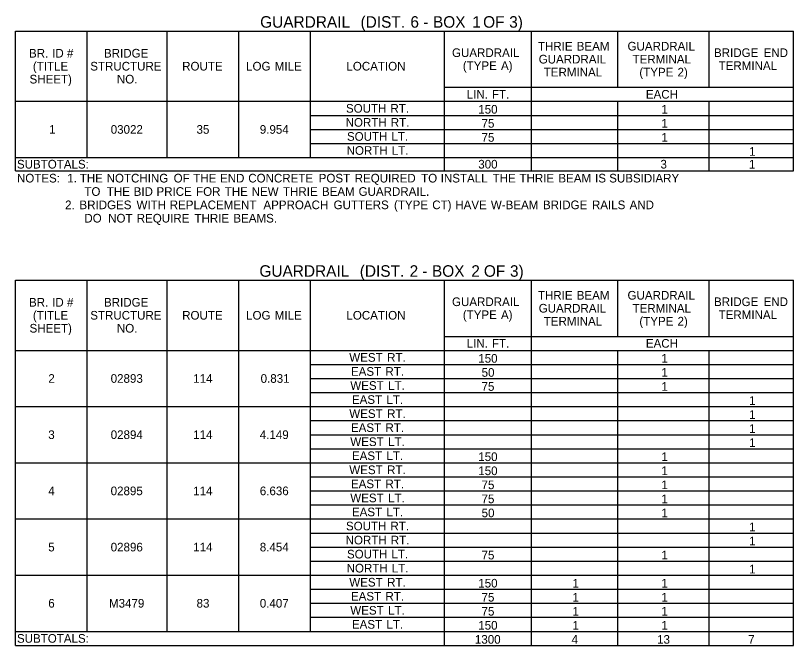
# Model space of a CAD drawing. Extents: x 542596 to 1930787, y -1948294 to 596640.
# Drawn here: x 546811 to 547351, y -1946617 to -1946180 of the extents above; entities that cross this region are included whole.
import ezdxf

# ---------------------------------------------------------------- set-up
doc = ezdxf.new("R2010")
doc.units = 0
doc.layers.add('Default', color=7, linetype='Continuous')

msp = doc.modelspace()

# ---------------------------------------------------------------- linework, layer by layer
at = {"layer": 'Default'}
for p, q in [((546810.99, -1946190.4), (547351.14, -1946190.4)), ((546810.99, -1946287.41), (546810.99, -1946190.4)), ((546810.99, -1946287.41), (546810.99, -1946190.4)), ((546860.71, -1946278.15), (546860.71, -1946190.4)), ((546916.29, -1946278.15), (546916.29, -1946190.4)), ((546966.01, -1946278.15), (546966.01, -1946190.4)), ((547015.74, -1946278.15), (547015.74, -1946190.4)), ((547108.85, -1946287.41), (547108.85, -1946190.4)), ((547169.3, -1946287.41), (547169.3, -1946190.4)), ((547229.26, -1946229.4), (547229.26, -1946190.4)), ((547292.64, -1946229.4), (547292.64, -1946190.4)), ((547351.14, -1946287.41), (547351.14, -1946190.4)), ((547108.85, -1946229.4), (547351.14, -1946229.4)), ((547169.3, -1946278.15), (547169.3, -1946229.4)), ((546810.99, -1946239.15), (547351.14, -1946239.15)), ((547229.26, -1946278.15), (547229.26, -1946239.15)), ((547229.26, -1946287.41), (547229.26, -1946239.15)), ((547292.64, -1946278.15), (547292.64, -1946239.15)), ((547292.64, -1946287.41), (547292.64, -1946239.15)), ((547015.74, -1946248.9), (547351.14, -1946248.9)), ((547015.74, -1946258.65), (547351.14, -1946258.65)), ((547015.74, -1946268.4), (547351.14, -1946268.4)), ((546810.99, -1946278.15), (547292.64, -1946278.15)), ((546810.99, -1946278.15), (547229.26, -1946278.15)), ((547229.26, -1946278.15), (547351.14, -1946278.15)), ((546810.99, -1946287.41), (547351.14, -1946287.41)), ((546810.99, -1946363.24), (547351.14, -1946363.24)), ((546810.99, -1946616.74), (546810.99, -1946363.24)), ((546810.99, -1946616.74), (546810.99, -1946363.24)), ((546860.71, -1946606.99), (546860.71, -1946363.24)), ((546916.29, -1946606.99), (546916.29, -1946363.24)), ((546966.01, -1946606.99), (546966.01, -1946363.24)), ((547015.74, -1946606.99), (547015.74, -1946363.24)), ((547108.85, -1946616.74), (547108.85, -1946363.24)), ((547169.3, -1946616.74), (547169.3, -1946363.24)), ((547229.26, -1946402.24), (547229.26, -1946363.24)), ((547292.64, -1946402.24), (547292.64, -1946363.24)), ((547351.14, -1946606.99), (547351.14, -1946363.24)), ((547108.85, -1946402.24), (547351.14, -1946402.24)), ((547169.3, -1946616.74), (547169.3, -1946402.24)), ((546810.99, -1946411.99), (547351.14, -1946411.99)), ((547229.26, -1946616.74), (547229.26, -1946411.99)), ((547229.26, -1946616.74), (547229.26, -1946411.99)), ((547292.64, -1946616.74), (547292.64, -1946411.99)), ((547015.74, -1946421.74), (547351.14, -1946421.74)), ((547292.64, -1946431.49), (547292.64, -1946421.74)), ((547015.74, -1946431.49), (547351.14, -1946431.49)), ((547015.74, -1946441.24), (547351.14, -1946441.24)), ((547292.64, -1946450.99), (547292.64, -1946441.24)), ((546810.99, -1946450.99), (547351.14, -1946450.99)), ((546966.01, -1946450.99), (547108.85, -1946450.99)), ((547108.85, -1946450.99), (547351.14, -1946450.99)), ((547015.74, -1946460.74), (547351.14, -1946460.74)), ((547015.74, -1946470.49), (547351.14, -1946470.49)), ((547015.74, -1946480.24), (547351.14, -1946480.24)), ((546810.99, -1946489.99), (547351.14, -1946489.99)), ((547015.74, -1946489.99), (547108.85, -1946489.99)), ((547108.85, -1946489.99), (547351.14, -1946489.99)), ((547015.74, -1946499.74), (547351.14, -1946499.74)), ((547015.74, -1946509.49), (547351.14, -1946509.49)), ((547015.74, -1946519.24), (547351.14, -1946519.24)), ((547292.64, -1946528.99), (547292.64, -1946519.24)), ((546810.99, -1946528.99), (547351.14, -1946528.99)), ((547015.74, -1946528.99), (547108.85, -1946528.99)), ((547108.85, -1946528.99), (547351.14, -1946528.99)), ((547015.74, -1946538.74), (547351.14, -1946538.74)), ((547292.64, -1946548.49), (547292.64, -1946538.74)), ((547015.74, -1946548.49), (547351.14, -1946548.49)), ((547015.74, -1946558.24), (547351.14, -1946558.24)), ((546810.99, -1946567.99), (547351.14, -1946567.99)), ((547015.74, -1946567.99), (547108.85, -1946567.99)), ((547108.85, -1946567.99), (547351.14, -1946567.99)), ((547015.74, -1946577.74), (547351.14, -1946577.74)), ((547015.74, -1946587.49), (547351.14, -1946587.49)), ((547015.74, -1946597.24), (547351.14, -1946597.24)), ((546810.99, -1946606.99), (547351.14, -1946606.99)), ((547292.64, -1946616.74), (547292.64, -1946606.99)), ((547351.14, -1946616.74), (547351.14, -1946606.99)), ((546810.99, -1946616.74), (547351.14, -1946616.74))]:
    msp.add_line(p, q, dxfattribs=at)

# ---------------------------------------------------------------- texts
for s, height, p in [('GUARDRAIL', 8, (546980.84, -1946188.06)), (' (DIST.', 8, (547047.57, -1946188.06)), (' 6', 8, (547082.19, -1946188.06)), (' BOX', 8, (547097.86, -1946188.06)), (' 1', 8, (547125.17, -1946188.06)), (' OF', 8, (547132.68, -1946188.06)), (' 3)', 8, (547150.79, -1946188.06)), (' -', 8, (547091.11, -1946188.06)), ('THRIE', 6, (547173.71, -1946203.9)), (' BEAM', 6, (547198.44, -1946203.9)), ('GUARDRAIL', 6, (547235.93, -1946203.9)), ('BR.', 6, (546820.33, -1946208.77)), (' ID', 6, (546834.19, -1946208.77)), (' #', 6, (546844.48, -1946208.77)), ('BRIDGE', 6, (546872.4, -1946208.77)), ('GUARDRAIL', 6, (547114.05, -1946208.4)), ('BRIDGE', 6, (547295.98, -1946208.4)), (' END', 6, (547328.18, -1946208.4)), ('GUARDRAIL', 6, (547174.26, -1946212.9)), ('TERMINAL', 6, (547239.42, -1946212.9)), ('(TITLE', 6, (546823.02, -1946217.77)), ('STRUCTURE', 6, (546862.86, -1946217.77)), ('ROUTE', 6, (546926.68, -1946217.77)), ('LOG', 6, (546971.08, -1946217.77)), (' MILE', 6, (546988.73, -1946217.77)), ('LOCATION', 6, (547040.74, -1946217.77)), ('(TYPE', 6, (547121.57, -1946217.4)), (' A)', 6, (547145.84, -1946217.4)), ('TERMINAL', 6, (547299.19, -1946217.4)), ('TERMINAL', 6, (547177.75, -1946221.9)), ('(TYPE', 6, (547244.14, -1946221.9)), (' 2)', 6, (547268.42, -1946221.9)), ('SHEET)', 6, (546820.69, -1946226.77)), ('NO.', 6, (546881.34, -1946226.77)), ('LIN.', 6, (547124.29, -1946237.27)), (' FT.', 6, (547139.54, -1946237.27)), ('EACH', 6, (547248.66, -1946237.27)), ('SOUTH', 6, (547040.41, -1946247.02)), (' RT.', 6, (547069.08, -1946247.02)), ('150', 6, (547132.29, -1946247.7)), ('1', 6, (547259.39, -1946247.7)), ('NORTH', 6, (547040.18, -1946256.77)), (' RT.', 6, (547069.31, -1946256.77)), ('75', 6, (547134.58, -1946257.45)), ('1', 6, (547259.39, -1946257.45)), ('1', 6, (546834.29, -1946261.65)), ('03022', 6, (546877.07, -1946261.65)), ('35', 6, (546936.66, -1946261.65)), ('9.954', 6, (546980.59, -1946261.65)), ('SOUTH', 6, (547041.11, -1946266.52)), (' LT.', 6, (547069.78, -1946266.52)), ('75', 6, (547134.58, -1946267.2)), ('1', 6, (547259.39, -1946267.2)), ('NORTH', 6, (547040.88, -1946276.27)), (' LT.', 6, (547070.01, -1946276.27)), ('1', 6, (547320.33, -1946276.95)), ('SUBTOTALS:', 6, (546811.96, -1946285.78)), ('300', 6, (547132.29, -1946285.78)), ('3', 6, (547258.8, -1946285.78)), ('1', 6, (547320.24, -1946285.78)), ('NOTES:', 6, (546811.96, -1946295.47)), ('  1.', 6, (546842.44, -1946295.47)), (' THE', 6, (546853.35, -1946295.47)), (' NOTCHING', 6, (546872, -1946295.47)), (' OF', 6, (546918.52, -1946295.47)), (' THE', 6, (546932.1, -1946295.47)), (' END', 6, (546950.75, -1946295.47)), (' CONCRETE', 6, (546970.34, -1946295.47)), (' POST', 6, (547019.26, -1946295.47)), (' REQUIRED', 6, (547044.25, -1946295.47)), (' TO', 6, (547090.39, -1946295.47)), (' INSTALL', 6, (547103.98, -1946295.47)), (' THE', 6, (547140.02, -1946295.47)), (' THRIE', 6, (547158.67, -1946295.47)), (' BEAM', 6, (547185.7, -1946295.47)), (' IS', 6, (547211.16, -1946295.47)), (' SUBSIDIARY', 6, (547220.97, -1946295.47)), ('                     TO', 6, (546811.96, -1946304.74)), (' THE', 6, (546872.11, -1946304.74)), (' BID', 6, (546890.76, -1946304.74)), (' PRICE', 6, (546906.62, -1946304.74)), (' FOR', 6, (546934.12, -1946304.74)), (' THE', 6, (546954.03, -1946304.74)), (' NEW', 6, (546972.68, -1946304.74)), (' THRIE', 6, (546994.47, -1946304.74)), (' BEAM', 6, (547021.5, -1946304.74)), (' GUARDRAIL.', 6, (547046.96, -1946304.74)), ('               2.', 6, (546811.96, -1946314)), (' BRIDGES', 6, (546853.13, -1946314)), (' WITH', 6, (546892.76, -1946314)), (' REPLACEMENT', 6, (546915.83, -1946314)), (' APPROACH', 6, (546980.88, -1946314)), (' GUTTERS', 6, (547029.59, -1946314)), (' (TYPE', 6, (547071.54, -1946314)), (' CT)', 6, (547098.11, -1946314)), (' HAVE', 6, (547114.1, -1946314)), (' W-BEAM', 6, (547138.82, -1946314)), (' BRIDGE', 6, (547174.98, -1946314)), (' RAILS', 6, (547209, -1946314)), (' AND', 6, (547235.12, -1946314)), ('                     DO', 6, (546811.96, -1946323.26)), (' NOT', 6, (546873.05, -1946323.26)), (' REQUIRE', 6, (546892.9, -1946323.26)), (' THRIE', 6, (546932.98, -1946323.26)), (' BEAMS.', 6, (546960.01, -1946323.26)), ('GUARDRAIL', 8, (546980.3, -1946360.9)), (' (DIST.', 8, (547047.03, -1946360.9)), (' 2', 8, (547081.65, -1946360.9)), (' BOX', 8, (547097.15, -1946360.9)), (' 2', 8, (547124.47, -1946360.9)), (' OF', 8, (547133.22, -1946360.9)), (' 3)', 8, (547151.33, -1946360.9)), (' -', 8, (547090.41, -1946360.9)), ('THRIE', 6, (547173.71, -1946376.74)), (' BEAM', 6, (547198.44, -1946376.74)), ('GUARDRAIL', 6, (547235.93, -1946376.74)), ('BR.', 6, (546820.33, -1946381.62)), (' ID', 6, (546834.19, -1946381.62)), (' #', 6, (546844.48, -1946381.62)), ('BRIDGE', 6, (546872.4, -1946381.62)), ('GUARDRAIL', 6, (547114.05, -1946381.24)), ('BRIDGE', 6, (547295.98, -1946381.24)), (' END', 6, (547328.18, -1946381.24)), ('GUARDRAIL', 6, (547174.26, -1946385.74)), ('TERMINAL', 6, (547239.42, -1946385.74)), ('(TITLE', 6, (546823.02, -1946390.62)), ('STRUCTURE', 6, (546862.86, -1946390.62)), ('ROUTE', 6, (546926.68, -1946390.62)), ('LOG', 6, (546971.08, -1946390.62)), (' MILE', 6, (546988.73, -1946390.62)), ('LOCATION', 6, (547040.74, -1946390.62)), ('(TYPE', 6, (547121.57, -1946390.24)), (' A)', 6, (547145.84, -1946390.24)), ('TERMINAL', 6, (547299.19, -1946390.24)), ('TERMINAL', 6, (547177.75, -1946394.74)), ('(TYPE', 6, (547244.14, -1946394.74)), (' 2)', 6, (547268.42, -1946394.74)), ('SHEET)', 6, (546820.69, -1946399.62)), ('NO.', 6, (546881.34, -1946399.62)), ('LIN.', 6, (547124.29, -1946410.12)), (' FT.', 6, (547139.54, -1946410.12)), ('EACH', 6, (547248.66, -1946410.12)), ('WEST', 6, (547042.72, -1946419.87)), (' RT.', 6, (547066.77, -1946419.87)), ('150', 6, (547132.29, -1946420.54)), ('1', 6, (547259.39, -1946420.54)), ('EAST', 6, (547043.88, -1946429.62)), (' RT.', 6, (547065.61, -1946429.62)), ('50', 6, (547134.62, -1946430.29)), ('1', 6, (547259.39, -1946430.29)), ('2', 6, (546833.74, -1946434.49)), ('02893', 6, (546877.04, -1946434.49)), ('114', 6, (546934.36, -1946434.49)), ('0.831', 6, (546981.16, -1946434.49)), ('WEST', 6, (547043.42, -1946439.37)), (' LT.', 6, (547067.47, -1946439.37)), ('75', 6, (547134.58, -1946440.04)), ('1', 6, (547259.39, -1946440.04)), ('EAST', 6, (547044.57, -1946449.12)), (' LT.', 6, (547066.31, -1946449.12)), ('1', 6, (547320.33, -1946449.79)), ('WEST', 6, (547042.72, -1946458.87)), (' RT.', 6, (547066.77, -1946458.87)), ('1', 6, (547320.33, -1946459.54)), ('EAST', 6, (547043.88, -1946468.62)), (' RT.', 6, (547065.61, -1946468.62)), ('3', 6, (546833.71, -1946473.49)), ('02894', 6, (546877.05, -1946473.49)), ('114', 6, (546934.36, -1946473.49)), ('4.149', 6, (546980.58, -1946473.49)), ('1', 6, (547320.33, -1946469.29)), ('WEST', 6, (547043.42, -1946478.37)), (' LT.', 6, (547067.47, -1946478.37)), ('1', 6, (547320.33, -1946479.04)), ('EAST', 6, (547044.57, -1946488.12)), (' LT.', 6, (547066.31, -1946488.12)), ('150', 6, (547132.29, -1946488.79)), ('1', 6, (547259.39, -1946488.79)), ('WEST', 6, (547042.72, -1946497.87)), (' RT.', 6, (547066.77, -1946497.87)), ('150', 6, (547132.29, -1946498.54)), ('1', 6, (547259.39, -1946498.54)), ('EAST', 6, (547043.88, -1946507.62)), (' RT.', 6, (547065.61, -1946507.62)), ('75', 6, (547134.58, -1946508.29)), ('1', 6, (547259.39, -1946508.29)), ('4', 6, (546833.72, -1946512.49)), ('02895', 6, (546877.02, -1946512.49)), ('114', 6, (546934.36, -1946512.49)), ('6.636', 6, (546980.58, -1946512.49)), ('WEST', 6, (547043.42, -1946517.37)), (' LT.', 6, (547067.47, -1946517.37)), ('75', 6, (547134.58, -1946518.04)), ('1', 6, (547259.39, -1946518.04)), ('EAST', 6, (547044.57, -1946527.12)), (' LT.', 6, (547066.31, -1946527.12)), ('50', 6, (547134.62, -1946527.79)), ('1', 6, (547259.39, -1946527.79)), ('SOUTH', 6, (547040.41, -1946536.87)), (' RT.', 6, (547069.08, -1946536.87)), ('1', 6, (547320.33, -1946537.54)), ('NORTH', 6, (547040.18, -1946546.62)), (' RT.', 6, (547069.31, -1946546.62)), ('1', 6, (547320.33, -1946547.29)), ('5', 6, (546833.69, -1946551.49)), ('02896', 6, (546877.04, -1946551.49)), ('114', 6, (546934.36, -1946551.49)), ('8.454', 6, (546980.59, -1946551.49)), ('SOUTH', 6, (547041.11, -1946556.37)), (' LT.', 6, (547069.78, -1946556.37)), ('75', 6, (547134.58, -1946557.04)), ('1', 6, (547259.39, -1946557.04)), ('NORTH', 6, (547040.88, -1946566.12)), (' LT.', 6, (547070.01, -1946566.12)), ('1', 6, (547320.33, -1946566.79)), ('WEST', 6, (547042.72, -1946575.87)), (' RT.', 6, (547066.77, -1946575.87)), ('150', 6, (547132.29, -1946576.54)), ('1', 6, (547197.72, -1946576.54)), ('1', 6, (547259.39, -1946576.54)), ('EAST', 6, (547043.88, -1946585.62)), (' RT.', 6, (547065.61, -1946585.62)), ('75', 6, (547134.58, -1946586.29)), ('1', 6, (547197.72, -1946586.29)), ('1', 6, (547259.39, -1946586.29)), ('6', 6, (546833.71, -1946590.49)), ('M3479', 6, (546875.87, -1946590.49)), ('83', 6, (546936.68, -1946590.49)), ('0.407', 6, (546980.58, -1946590.49)), ('WEST', 6, (547043.42, -1946595.37)), (' LT.', 6, (547067.47, -1946595.37)), ('75', 6, (547134.58, -1946596.04)), ('1', 6, (547197.72, -1946596.04)), ('1', 6, (547259.39, -1946596.04)), ('EAST', 6, (547044.57, -1946605.12)), (' LT.', 6, (547066.31, -1946605.12)), ('150', 6, (547132.29, -1946605.79)), ('1', 6, (547197.72, -1946605.79)), ('1', 6, (547259.39, -1946605.79)), ('SUBTOTALS:', 6, (546811.96, -1946614.87)), ('1300', 6, (547129.96, -1946615.54)), ('4', 6, (547197.05, -1946615.54)), ('13', 6, (547256.47, -1946615.54)), ('7', 6, (547319.74, -1946615.54))]:
    msp.add_text(s, height=height, dxfattribs=at).set_placement(p)

doc.saveas('drawing.dxf')
